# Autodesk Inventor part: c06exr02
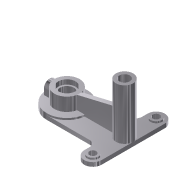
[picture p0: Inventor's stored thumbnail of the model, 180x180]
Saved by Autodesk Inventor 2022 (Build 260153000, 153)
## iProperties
Created: 2001-12
Part Number: c06exr02
Document SubType Name: Modeling
Material: Generic
Density: 1 g/cm^3
Appearance: Metal-AL-6061 (Polished)
Control State: 0
Master: False
Checked Out: False
Shininess: 77.0
Length Units: 11269
Angle Units: 11279
Time Units: 11290
Mass Units: 11283
Length Display Precision: 3
Angle Display Precision: 2
Density: 0.0
Volumn: 0.0
Area: 0.0
PropertySet Name: Model Information
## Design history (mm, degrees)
sketch "Sketch1"
  geometry: L1 (46.121, -53.4)-(46.121, 56.6); L2 (16.121, 56.6)-(16.121, 36.6); L3 (16.121, 36.6)-(-68.879, 36.6); L4 (-68.879, -33.4)-(16.121, -33.4); L5 (16.121, -33.4)-(16.121, -53.4); A1 r 15 centre (31.121, 56.6) between (46.121, 56.6) and (16.121, 56.6); A2 r 35 centre (-68.879, 1.6) between (-68.879, 36.6) and (-68.879, -33.4); A3 r 15 centre (31.121, -53.4) between (16.121, -53.4) and (46.121, -53.4)
  constraints: 10 end point, 6 point on circle, 5 tangent, 3 centre point, 3 parallel, 2 equal length, 1 equal radius, 1 perpendicular, 1 vertical
  dimensions: "d0" = 15 radius of A1; "d1" = 110 distance of L1.start L1.end; "d2" = 100 horizontal distance of A3.centre A2.centre; "d3" = 35 radius of A2
extrude "Extrusion1" new body sketch "Sketch1" distance "d4" = 7; taper "d5" = 0 deg
sketch "Sketch2"
  geometry: C1 r 10 at (31.121, 56.6); C2 r 10 at (31.121, -53.4); C3 r 35 at (-68.879, 1.6); A1 r 35 centre (-68.879, 1.6) between (-68.879, 36.6) and (-68.879, -33.4) reference; A2 r 15 centre (31.121, 56.6) between (46.121, 56.6) and (16.121, 56.6) reference; A3 r 15 centre (31.121, -53.4) between (16.121, -53.4) and (46.121, -53.4) reference
  constraints: 3 centre point, 3 concentric, 2 equal radius
  dimensions: "d45" = 20 diameter of C1
extrude "Extrusion2" join sketch "Sketch2" distance "d6" = 3; taper "d7" = 0 deg
sketch "Sketch3"
  geometry: C1 r 22 at (0, 0); 1 further point
  constraints: 1 centre point, 1 coincident
  dimensions: "d8" = 44 diameter of C1
extrude "Extrusion3" join sketch "Sketch3" distance "d9" = 23; taper "d10" = 0 deg
sketch "Sketch4"
  geometry: L1 (46.121, 56.6)-(46.121, -53.4) reference; L2 (-68.879, 36.6)-(16.121, 36.6) reference; C1 r 15 at (31.121, 1.6)
  constraints: 1 centre point
  dimensions: "d11" = 30 diameter of C1; "d12" = 15 distance from line of L1 C1.centre; "d13" = 35 distance from line of L2 C1.centre
extrude "Extrusion4" join sketch "Sketch4" distance "d14" = 88; taper "d15" = 0 deg
workplane "Work Plane1"
sketch "Sketch5"
  geometry: L1 (22, 33.1)-(85, 48); L2 (0, 7)-(35, 7) reference; L3 (85, 0)-(85, 7) reference; L4 (115, 0)-(115, 7) reference; L5 (115, 0)-(85, 0) reference
  constraints: 2 end point
  dimensions: "d17" = 26.1 distance from line of L2 L1.start; "d18" = 63 distance from line of L3 L1.start; "d19" = 30 distance from line of L4 L1.end; "d20" = 48 distance from line of L5 L1.end
feature "Rib1" sketch "Sketch5" dims "d21" = 1, "d22" = 8
workplane "Work Plane2"
workplane "Work Plane3"
sketch "Sketch7"
  geometry: L1 (10, 0)-(10, 10); L2 (-10, 10)-(-10, 0); L3 (-10, 0)-(10, 0); L4 (55, -10)-(55, -3) reference; A1 r 10 centre (0, 10) between (10, 10) and (-10, 10); 2 further points
  constraints: 6 end point, 2 point on circle, 2 tangent, 1 centre point, 1 parallel, 1 perpendicular, 1 vertical
  dimensions: "d30" = 10 radius of A1; "d34" = 55 distance from line of L4 A1.centre; "d35" = 10 distance of L1.start L1.end
extrude "Extrusion6" join sketch "Sketch7" stored distance "d36" = 88; taper "d37" = 0 deg
sketch "Sketch8"
  geometry: C1 r 10 at (0, 0) reference
hole "Hole1" sketch "Sketch8" at (0, 0) diameter "d38" = 12; stored, may be unused: countersink angle "d42" = 82 deg, drill point angle "d44" = 118 deg; dims "d39" = 6, "d40" = 4, "d41" = 2, "d43" = 8
mirror "Mirror1"
sketch "Sketch9"
  geometry: C1 r 10 at (0, 0)
  constraints: 1 centre point
hole "Hole2" sketch "Sketch9" at (0, 0) diameter "d52" = 18; stored, may be unused: drill point angle "d47" = 118 deg, countersink angle "d48" = 82 deg; dims "d46" = 6, "d49" = 2, "d50" = 4, "d51" = 8
sketch "Sketch10"
  geometry: C1 r 10 at (0, 0)
  constraints: 1 centre point
hole "Hole3" sketch "Sketch10" at (0, 0) diameter "d59" = 24; stored, may be unused: drill point angle "d54" = 118 deg, countersink angle "d55" = 82 deg; dims "d53" = 6, "d56" = 8, "d57" = 30, "d58" = 8
sketch "Sketch11"
  geometry: C1 r 10 at (0, 0)
  constraints: 1 centre point
hole "Hole4" sketch "Sketch11" at (0, 0) diameter "d66" = 10; stored, may be unused: drill point angle "d61" = 0 deg, countersink angle "d62" = 82 deg; dims "d60" = 6, "d63" = 2, "d64" = 4, "d65" = 8
fillet "Fillet1" dims "d67" = 10
body "Solid1"
other parameters: "d16" = -35, "d29" = -8
